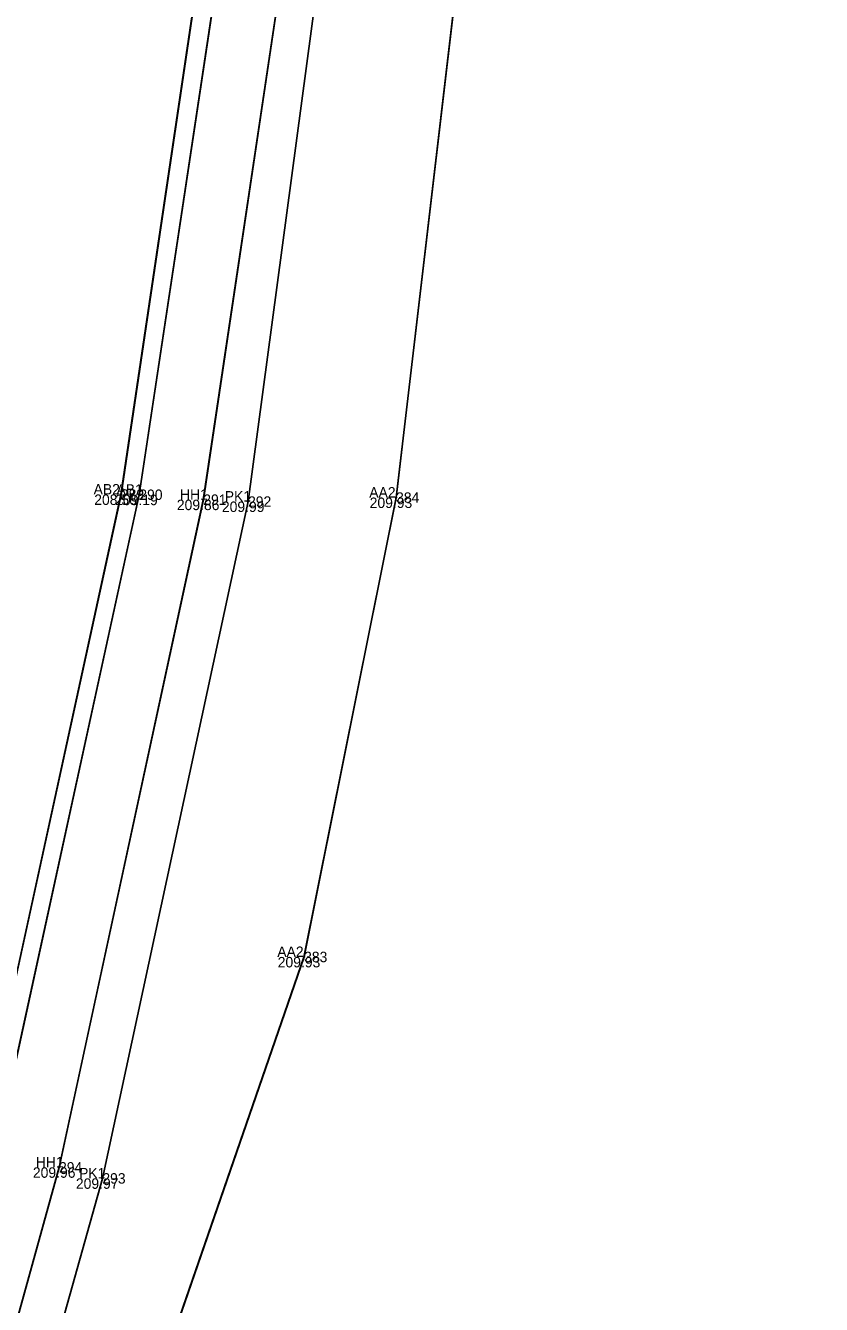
# Model space of a CAD drawing. Extents: x -263091 to -262565, y -1238731 to -1237092.
# Drawn here: x -262832.04 to -262816.76, y -1238071.97 to -1238047.41 of the extents above; entities that cross this region are included whole.
import ezdxf

# ---------------------------------------------------------------- set-up
doc = ezdxf.new("R2010")
doc.units = 0
for name, color, linetype in [('02_Oplotenie', 7, 'Continuous'), ('03_Asfalt', 7, 'Continuous'), ('05_Hrana_terénu', 7, 'Continuous'), ('09_Múrik', 7, 'Continuous'), ('Groma (21)', 7, 'Continuous'), ('Groma (22)', 7, 'Continuous'), ('Groma (23)', 7, 'Continuous'), ('Groma (24)', 7, 'Continuous'), ('U003_Asfalt', 7, 'Continuous'), ('U003_Betónové_múriky', 7, 'Continuous'), ('U003_Betónové_panely', 7, 'Continuous'), ('U003_Zeleň_vnútro', 7, 'Continuous'), ('U003_Zeleň_zatrávňovač', 7, 'Continuous'), ('U005_Betóny_prídavné', 7, 'Continuous')]:
    doc.layers.add(name, color=color, linetype=linetype)

msp = doc.modelspace()

# ---------------------------------------------------------------- linework, layer by layer
at = {"layer": '02_Oplotenie'}
msp.add_lwpolyline([(-262819.762, -1237938.034), (-262820.788, -1237960.675), (-262821.837, -1237980.919), (-262823.308, -1238002.106), (-262824.582, -1238026.068), (-262825.82, -1238041.973), (-262827.772, -1238056.552), (-262830.57, -1238069.546), (-262834.589, -1238083.855), (-262839.328, -1238095.835), (-262848.782, -1238120.942), (-262853.684, -1238135.175), (-262859.896, -1238152.781), (-262867.698, -1238174.329), (-262874.833, -1238193.487), (-262881.88, -1238212.036), (-262887.174, -1238225.693), (-262888.829, -1238230.138)], dxfattribs=at)
at = {"layer": '03_Asfalt'}
msp.add_lwpolyline([(-262816.76, -1237934.791), (-262817.067, -1237940.584), (-262818.198, -1237960.603), (-262819.351, -1237980.318), (-262820.259, -1237997.242), (-262821.106, -1238014.516), (-262822.726, -1238037.787), (-262824.929, -1238056.475), (-262826.695, -1238065.295), (-262832.135, -1238081.046), (-262834.142, -1238085.994), (-262836.111, -1238090.171)], dxfattribs=at)
at = {"layer": '05_Hrana_terénu'}
msp.add_lwpolyline([(-262849.564, -1238120.544), (-262839.894, -1238095.583), (-262835.301, -1238083.403), (-262831.402, -1238069.334), (-262828.632, -1238056.516), (-262826.436, -1238041.83), (-262825.08, -1238026.06), (-262823.863, -1238001.967), (-262822.633, -1237980.847), (-262821.298, -1237960.54), (-262820.334, -1237939.047), (-262819.871, -1237937.657)], dxfattribs=at)
at = {"layer": '09_Múrik'}
for points in [[(-262840.924, -1238094.827), (-262836.941, -1238083.068), (-262832.969, -1238069.042), (-262830.214, -1238056.416), (-262828.063, -1238041.942), (-262826.83, -1238026.465), (-262825.494, -1238001.855), (-262824.316, -1237980.84), (-262823.031, -1237960.337), (-262821.719, -1237936.336)], [(-262840.6, -1238094.732), (-262836.43, -1238082.967), (-262832.633, -1238069.1), (-262829.86, -1238056.421), (-262827.688, -1238042.018), (-262826.338, -1238026.448), (-262825.108, -1238001.872), (-262823.89, -1237980.741), (-262822.602, -1237960.47), (-262821.253, -1237936.39)]]:
    msp.add_lwpolyline(points, dxfattribs=at)
at = {"layer": 'Groma (21)'}
for centre in [(-262830.214, -1238056.416), (-262829.86, -1238056.421), (-262824.929, -1238056.475), (-262828.632, -1238056.516), (-262827.772, -1238056.552), (-262826.695, -1238065.295), (-262831.402, -1238069.334), (-262830.57, -1238069.546)]:
    msp.add_circle(centre, 0.01, dxfattribs=at)
at = {"layer": 'U003_Asfalt'}
for points in [[(-262836.86, -1238089.78), (-262834.59, -1238083.86), (-262830.57, -1238069.55), (-262827.77, -1238056.55), (-262825.82, -1238041.97), (-262824.58, -1238026.07), (-262823.31, -1238002.11), (-262821.84, -1237980.92), (-262820.79, -1237960.68), (-262819.76, -1237938.03), (-262819.87, -1237937.66), (-262818.51, -1237937.77), (-262818.3, -1237934.7)], [(-262816.76, -1237934.79), (-262817.07, -1237940.58), (-262818.2, -1237960.6), (-262819.35, -1237980.32), (-262820.26, -1237997.24), (-262821.11, -1238014.52), (-262822.73, -1238037.79), (-262824.93, -1238056.48), (-262826.7, -1238065.3), (-262832.14, -1238081.05), (-262834.14, -1238085.99), (-262836.11, -1238090.17), (-262836.86, -1238089.78)], [(-262821.11, -1238014.52), (-262822.73, -1238037.79), (-262824.93, -1238056.48), (-262826.7, -1238065.3), (-262832.14, -1238081.05), (-262834.14, -1238085.99), (-262836.11, -1238090.17), (-262836.86, -1238089.78), (-262834.59, -1238083.86), (-262830.57, -1238069.55), (-262827.77, -1238056.55), (-262825.82, -1238041.97), (-262824.58, -1238026.07), (-262823.31, -1238002.11)]]:
    msp.add_lwpolyline(points, dxfattribs=at)
at = {"layer": 'U003_Betónové_múriky'}
msp.add_lwpolyline([(-262821.25, -1237936.39), (-262822.6, -1237960.47), (-262823.89, -1237980.74), (-262825.11, -1238001.87), (-262826.34, -1238026.45), (-262827.69, -1238042.02), (-262829.86, -1238056.42), (-262832.63, -1238069.1), (-262836.43, -1238082.97), (-262840.6, -1238094.73), (-262840.92, -1238094.83), (-262836.94, -1238083.07), (-262832.97, -1238069.04), (-262830.21, -1238056.42), (-262828.06, -1238041.94), (-262826.83, -1238026.47), (-262825.49, -1238001.86), (-262824.32, -1237980.84), (-262823.03, -1237960.34), (-262821.72, -1237936.34)], close=True, dxfattribs=at)
msp.add_lwpolyline([(-262821.72, -1237936.34), (-262821.25, -1237936.39), (-262822.6, -1237960.47), (-262823.89, -1237980.74), (-262825.11, -1238001.87), (-262826.34, -1238026.45), (-262827.69, -1238042.02), (-262829.86, -1238056.42), (-262832.63, -1238069.1), (-262836.43, -1238082.97), (-262840.6, -1238094.73), (-262840.92, -1238094.83), (-262836.94, -1238083.07), (-262832.97, -1238069.04), (-262830.21, -1238056.42), (-262828.06, -1238041.94), (-262826.83, -1238026.47), (-262825.49, -1238001.86), (-262824.32, -1237980.84), (-262823.03, -1237960.34), (-262821.72, -1237936.34)], dxfattribs=at)
at = {"layer": 'U003_Betónové_panely'}
msp.add_lwpolyline([(-262822, -1237934.47), (-262822.23, -1237936.28), (-262821.72, -1237936.34), (-262823.03, -1237960.34), (-262824.32, -1237980.84), (-262825.49, -1238001.86), (-262826.83, -1238026.47), (-262828.06, -1238041.94), (-262830.21, -1238056.42), (-262832.97, -1238069.04), (-262836.94, -1238083.07), (-262840.92, -1238094.83), (-262840.6, -1238094.73), (-262841.76, -1238095.81), (-262851.46, -1238119.84), (-262857.2, -1238134.12), (-262863.32, -1238150.73), (-262871.41, -1238173.11), (-262878.16, -1238192.14), (-262884.61, -1238210.94), (-262889.86, -1238225.24), (-262892.75, -1238232.5), (-262895.19, -1238238.55), (-262900.83, -1238252.4)], dxfattribs=at)
msp.add_lwpolyline([(-262822, -1237934.47), (-262822.23, -1237936.28), (-262821.72, -1237936.34), (-262823.03, -1237960.34), (-262824.32, -1237980.84), (-262825.49, -1238001.86), (-262826.83, -1238026.47), (-262828.06, -1238041.94), (-262830.21, -1238056.42), (-262832.97, -1238069.04), (-262836.94, -1238083.07), (-262840.92, -1238094.83), (-262840.6, -1238094.73), (-262841.76, -1238095.81), (-262851.46, -1238119.84), (-262857.2, -1238134.12), (-262863.32, -1238150.73), (-262871.41, -1238173.11), (-262878.16, -1238192.14), (-262884.61, -1238210.94), (-262889.86, -1238225.24), (-262892.75, -1238232.5), (-262895.19, -1238238.55), (-262900.83, -1238252.4)], dxfattribs=at)
at = {"layer": 'U003_Zeleň_vnútro'}
msp.add_lwpolyline([(-262849.56, -1238120.54), (-262839.89, -1238095.58), (-262835.3, -1238083.4), (-262831.4, -1238069.33), (-262828.63, -1238056.52), (-262826.44, -1238041.83), (-262825.08, -1238026.06), (-262823.86, -1238001.97), (-262822.63, -1237980.85), (-262821.3, -1237960.54), (-262820.33, -1237939.05), (-262819.87, -1237937.66), (-262819.76, -1237938.03), (-262820.79, -1237960.68), (-262821.84, -1237980.92), (-262823.31, -1238002.11), (-262824.58, -1238026.07), (-262825.82, -1238041.97), (-262827.77, -1238056.55), (-262830.57, -1238069.55), (-262834.59, -1238083.86), (-262839.33, -1238095.84), (-262848.78, -1238120.94)], dxfattribs=at)
msp.add_lwpolyline([(-262849.56, -1238120.54), (-262839.89, -1238095.58), (-262835.3, -1238083.4), (-262831.4, -1238069.33), (-262828.63, -1238056.52), (-262826.44, -1238041.83), (-262825.08, -1238026.06), (-262823.86, -1238001.97), (-262822.63, -1237980.85), (-262821.3, -1237960.54), (-262820.33, -1237939.05), (-262819.87, -1237937.66), (-262819.76, -1237938.03), (-262820.79, -1237960.68), (-262821.84, -1237980.92), (-262823.31, -1238002.11), (-262824.58, -1238026.07), (-262825.82, -1238041.97), (-262827.77, -1238056.55), (-262830.57, -1238069.55), (-262834.59, -1238083.86), (-262839.33, -1238095.84), (-262848.78, -1238120.94)], dxfattribs=at)
at = {"layer": 'U003_Zeleň_zatrávňovač'}
for points in [[(-262851.46, -1238119.84), (-262841.76, -1238095.81), (-262840.6, -1238094.73), (-262836.43, -1238082.97), (-262832.63, -1238069.1), (-262829.86, -1238056.42), (-262827.69, -1238042.02), (-262826.34, -1238026.45), (-262825.11, -1238001.87)], [(-262823.86, -1238001.97), (-262825.08, -1238026.06), (-262826.44, -1238041.83), (-262828.63, -1238056.52), (-262831.4, -1238069.33), (-262835.3, -1238083.4), (-262839.89, -1238095.58), (-262849.56, -1238120.54)]]:
    msp.add_lwpolyline(points, dxfattribs=at)
at = {"layer": 'U005_Betóny_prídavné'}
for points in [[(-262851.46, -1238119.84), (-262841.76, -1238095.81), (-262840.6, -1238094.73), (-262836.43, -1238082.97), (-262832.63, -1238069.1), (-262829.86, -1238056.42), (-262827.69, -1238042.02), (-262826.34, -1238026.45), (-262825.11, -1238001.87)], [(-262823.86, -1238001.97), (-262825.08, -1238026.06), (-262826.44, -1238041.83), (-262828.63, -1238056.52), (-262831.4, -1238069.33), (-262835.3, -1238083.4), (-262839.89, -1238095.58), (-262849.56, -1238120.54)]]:
    msp.add_lwpolyline(points, dxfattribs=at)

# ---------------------------------------------------------------- texts
at = {"layer": 'Groma (22)'}
for s, p in [('289', (-262830.214, -1238056.516)), ('290', (-262829.86, -1238056.521)), ('291', (-262828.632, -1238056.616)), ('292', (-262827.772, -1238056.652)), ('384', (-262824.929, -1238056.575)), ('383', (-262826.695, -1238065.395)), ('294', (-262831.402, -1238069.434)), ('293', (-262830.57, -1238069.646))]:
    msp.add_text(s, height=0.2, dxfattribs=at).set_placement(p)
at = {"layer": 'Groma (23)'}
for s, p in [('208.56', (-262830.726, -1238056.616)), ('209.19', (-262830.324, -1238056.621)), ('209.86', (-262829.139, -1238056.716)), ('209.99', (-262828.274, -1238056.752)), ('209.93', (-262825.436, -1238056.675)), ('209.93', (-262827.202, -1238065.495)), ('209.96', (-262831.904, -1238069.534)), ('209.97', (-262831.078, -1238069.746))]:
    msp.add_text(s, height=0.2, dxfattribs=at).set_placement(p)
at = {"layer": 'Groma (24)'}
for s, p in [('AB2', (-262830.738, -1238056.416)), ('AB1', (-262830.298, -1238056.421)), ('HH1', (-262829.079, -1238056.516)), ('PK1', (-262828.219, -1238056.552)), ('AA2', (-262825.444, -1238056.475)), ('AA2', (-262827.21, -1238065.295)), ('HH1', (-262831.849, -1238069.334)), ('PK1', (-262831.017, -1238069.546))]:
    msp.add_text(s, height=0.2, dxfattribs=at).set_placement(p)

doc.saveas('drawing.dxf')
